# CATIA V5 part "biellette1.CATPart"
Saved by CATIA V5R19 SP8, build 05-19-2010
Part number: biellette1
Bounding box of the stored display mesh (mm): x 58 to 62, y 241.7 to 323.927, z 16.925 to 64.606
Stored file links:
  G:\EU_thinkMotion\CFAO_2010\MMS_groupe3\MMS_groupe3\A reprendre\amenand\amenand\biellette1.CATPart
  F:\thinkmotion CFAO v12.1\essuie_glace.CATProduct
  G:\EU_thinkMotion\CFAO_2010\MMS_groupe3\MMS_groupe3\A reprendre\amenand\amenand\squelette_biellette2.CATPart
  G:\EU_thinkMotion\CFAO_2010\MMS_groupe3\MMS_groupe3\A reprendre\amenand\amenand\squelette_biellette1.CATPart
  G:\EU_thinkMotion\CFAO_2010\MMS_groupe3\MMS_groupe3\A reprendre\amenand\amenand\bielle.CATPart
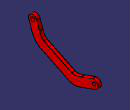
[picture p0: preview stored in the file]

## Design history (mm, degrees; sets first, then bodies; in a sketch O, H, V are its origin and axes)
Set1
  Plane1: linked copy from another document
  Point1: linked copy from another document
  Point2: linked copy from another document
  Line1 to Line3: linked copy from another document
  Plane2: linked copy from another document
  Point3: linked copy from another document
  Line4: linked copy from another document
  Line5: linked copy from another document
  Point4: linked copy from another document
Body1 (main body)
  Sketch1 on Plane2, origin (62, 0, 0), H (0, 1, 0), V (0, 0, 1)
    circle A1 centre (246.6094, 59.6969) radius 2.5
    arc A2 centre (246.6094, 59.6969) radius 5 from (251.3353, 61.3295) to (241.8834, 58.0643) ccw
    point P2 (246.6094, 59.6969)
    arc A3 centre (319.01, 29.5586) radius 5 from (320.6833, 24.8469) to (317.3366, 34.2703) ccw
    circle A4 centre (319.01, 29.5586) radius 2
    point P4 (319.01, 29.5586)
    line L1 (241.8834, 58.0643) -> (245.4785, 47.6577)
    reference projected line E1 (222.8803, 127.9829) -> (228.8403, 110.7307) from Line1
    line L2 (251.3353, 61.3295) -> (254.7093, 51.5628)
    line L3 (254.3023, 35.5411) -> (290.9041, 17.8476)
    reference projected line E2 (71.9785, 129.2812) -> (114.9095, 108.5282) from Line2
    line L4 (292.7571, 28.059) -> (259.6139, 44.0805)
    line L5 (320.6833, 24.8469) -> (307.7915, 20.2684)
    line L6 (317.3366, 34.2703) -> (304.4151, 29.6812)
    connectcurve C1
    connectcurve C2
    connectcurve C3
    connectcurve C4
    reference projected line E3 (252.594, 41.971) -> (295.525, 21.218) from Line2
    reference projected line E4 (295.525, 21.218) -> (319.01, 29.5586) from Line5
    reference projected point E5 (246.6094, 59.6969) from Point3
    reference projected point E6 (319.01, 29.5586) from Point4
    radius A1 = 2.5
    radius A2 = 5
    radius A3 = 5
    radius A4 = 2
    distance L3 L4 = 10
    distance C1 C2 = 10
    distance C4 C3 = 10
    parallelism: L1 E1, L3 E2, L6 L5, L2 L1, L3 E3, E4 L6
    tangency: L1 A2, L2 A2, L5 A3, L6 A3
    concentricity: A2 A1, A4 A3
    coincidence: E5 P2, P4 E6
  Pad1: profile Sketch1, direction (-1, 0, 0), length 4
